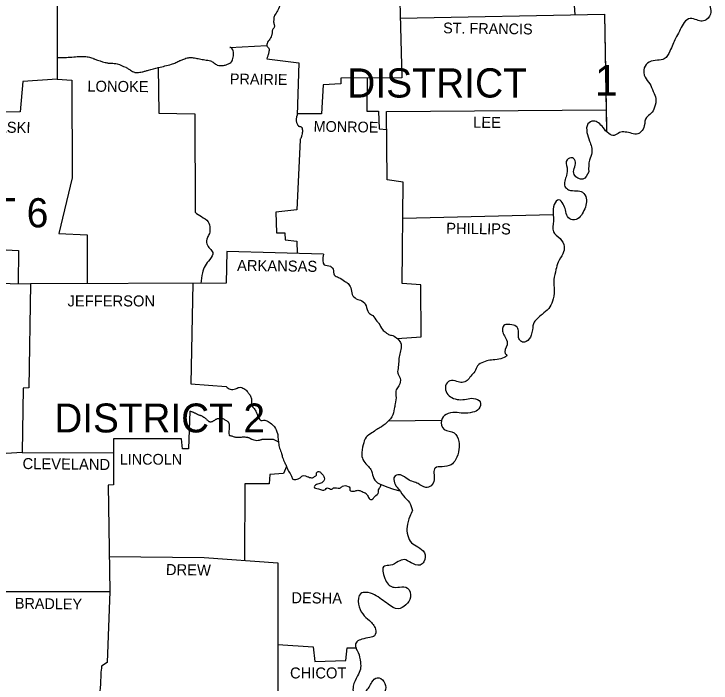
# Model space of a CAD drawing. Extents: x 6028666 to 6031787, y 5366484 to 5368484.
# Drawn here: x 6031401.8 to 6031674.1, y 5367817 to 5368078.3 of the extents above; entities that cross this region are included whole.
import ezdxf

# ---------------------------------------------------------------- set-up
doc = ezdxf.new("R2010")
doc.units = 0
doc.layers.add('2', color=7, linetype='Continuous')

msp = doc.modelspace()

# ---------------------------------------------------------------- linework, layer by layer
at = {"layer": '2'}
msp.add_line((6031548.15, 5367919.41), (6031568.9, 5367919.72), dxfattribs=at)
for points in [[(6031412.05, 5368281.89), (6031412.25, 5368257.49), (6031410.55, 5368257.39), (6031410.85, 5368232.49), (6031403.85, 5368231.49), (6031404.45, 5368224.79), (6031406.85, 5368221.69), (6031406.65, 5368213.79), (6031393.05, 5368213.29), (6031392.55, 5368201.09), (6031380.15, 5368200.69), (6031379.55, 5368185.89), (6031380.25, 5368184.69), (6031380.55, 5368161.09), (6031401.95, 5368159.69), (6031401.65, 5368107), (6031418.65, 5368106.5), (6031418.65, 5368052.9), (6031405.25, 5368051.9), (6031404.25, 5368040.1), (6031381.75, 5368040)], [(6031619.15, 5368123.08), (6031619.65, 5368084.2), (6031620.55, 5368083.6), (6031620.87, 5368078.06)], [(6031551.85, 5368108.2), (6031553.35, 5368053.4), (6031529.55, 5368053.3), (6031529.45, 5368051.1), (6031522.55, 5368050.7), (6031521.95, 5368039.3), (6031512.47, 5368039.3)], [(6031552.72, 5368076.69), (6031632.45, 5368078.3)], [(6031632.45, 5368078.3), (6031633.25, 5368034.5)], [(6031632.45, 5368078.3), (6031633.25, 5368034.5)], [(6031632.45, 5368078.3), (6031633.25, 5368034.5)], [(6031632.45, 5368078.3), (6031633.25, 5368034.5)], [(6031632.45, 5368078.3), (6031633.25, 5368034.5)], [(6031632.45, 5368078.3), (6031633.25, 5368034.5)], [(6031632.45, 5368078.3), (6031633.25, 5368034.5)], [(6031632.45, 5368078.3), (6031633.29, 5368032.49)], [(6031486.15, 5368065.3), (6031500.54, 5368065.99)], [(6031500.65, 5368060.8), (6031513.15, 5368059.2), (6031512.45, 5368038.8)], [(6031458.15, 5368057.5), (6031458.35, 5368039.6), (6031472.45, 5368039.3), (6031472.55, 5368000.9)], [(6031418.65, 5368052.9), (6031424.45, 5368052.5), (6031424.55, 5368014.3), (6031419.35, 5367992.6), (6031430.45, 5367992.1), (6031430.35, 5367972.99)], [(6031539.76, 5368053.34), (6031539.65, 5368040.4), (6031544.25, 5368040.4), (6031544.45, 5368033.5), (6031547.41, 5368033.19)], [(6031551.52, 5367951.6), (6031560.85, 5367952.2), (6031560.75, 5367972.5), (6031553.45, 5367973), (6031553.85, 5368012.7), (6031547.55, 5368013.6), (6031547.35, 5368040.3), (6031633.14, 5368040.9)], [(6031340.75, 5368027.94), (6031352.65, 5368027.2), (6031352.25, 5368014.7), (6031365.35, 5368014.2), (6031365.55, 5368003.3), (6031371.75, 5368002.8), (6031371.75, 5368000.9), (6031377.55, 5368000.5), (6031377.75, 5367993.5), (6031390.95, 5367993.5), (6031391.35, 5367986.6), (6031403.55, 5367986), (6031403.45, 5367972.98)], [(6031513.55, 5368029.2), (6031512.35, 5368001.8), (6031504.15, 5368000.9), (6031504.35, 5367992.8), (6031507.65, 5367992.9), (6031507.75, 5367990.1), (6031512.25, 5367989.6), (6031512.4, 5367984.77)], [(6031553.71, 5367998.59), (6031612.47, 5368000.05)], [(6031522.75, 5367984.5), (6031484.95, 5367985.5), (6031484.75, 5367973.2), (6031408.25, 5367972.9)], [(6031350.65, 5367959.7), (6031356.25, 5367960.5), (6031356.65, 5367963.9), (6031359.95, 5367964.5), (6031360.15, 5367966.5), (6031383.45, 5367967.2), (6031384.35, 5367973.3), (6031408.25, 5367972.9)], [(6031408.25, 5367972.9), (6031407.65, 5367932.3), (6031405.35, 5367932.2), (6031405.05, 5367907.1)], [(6031471.69, 5367973.15), (6031470.85, 5367933.9), (6031484.75, 5367932.8)], [(6031470.55, 5367923.2), (6031469.95, 5367908.5), (6031467.65, 5367908.5), (6031467.25, 5367912.4), (6031440.65, 5367912.4), (6031440.68, 5367906.9)], [(6031405.05, 5367907.1), (6031390.43, 5367906.2)], [(6031405.05, 5367907.1), (6031440.68, 5367906.9)], [(6031440.68, 5367906.9), (6031440.75, 5367894.4), (6031438.65, 5367894.3), (6031439.25, 5367852.8)], [(6031508.25, 5367901.6), (6031507.05, 5367898.9), (6031501.75, 5367898.4), (6031501.45, 5367894.8), (6031491.95, 5367894.8), (6031491.85, 5367864.9)], [(6031545.25, 5367894.5), (6031547.49, 5367893.62), (6031550.06, 5367892.73), (6031552.5, 5367892.11)], [(6031438.95, 5367866.4), (6031476.05, 5367866.1), (6031504.85, 5367863.9)], [(6031504.85, 5367863.9), (6031504.85, 5367804.1), (6031505.65, 5367746.67)], [(6031394.05, 5367852.7), (6031439.25, 5367852.8)], [(6031439.25, 5367852.8), (6031438.25, 5367825), (6031436.05, 5367823.6)], [(6031504.85, 5367832.03), (6031518.75, 5367831.2), (6031519.35, 5367825.4), (6031531.45, 5367825.8), (6031531.95, 5367830.7), (6031535.69, 5367830.7)]]:
    msp.add_lwpolyline(points, dxfattribs=at)
for points in [[(6031513.35, 5368119.8), (6031513.29, 5368118.96), (6031513.22, 5368118.14), (6031513.08, 5368117.31), (6031512.98, 5368116.9), (6031512.92, 5368116.7), (6031512.85, 5368116.5), (6031512.53, 5368116.13), (6031512.02, 5368115.95), (6031511.45, 5368115.82), (6031511.18, 5368115.73), (6031510.95, 5368115.6), (6031509.78, 5368114.56), (6031508.75, 5368113.4), (6031508.56, 5368112.92), (6031508.52, 5368112.38), (6031508.46, 5368111.85), (6031508.25, 5368111.4), (6031508.07, 5368111.24), (6031507.85, 5368111.13), (6031507.37, 5368110.99), (6031506.87, 5368110.85), (6031506.45, 5368110.6), (6031505.98, 5368110.12), (6031505.53, 5368109.62), (6031505.12, 5368109.08), (6031504.75, 5368108.5), (6031504.06, 5368107.08), (6031503.65, 5368105.6), (6031503.57, 5368104.1), (6031503.65, 5368102.6), (6031503.72, 5368101.73), (6031503.84, 5368100.88), (6031504.04, 5368100.03), (6031504.18, 5368099.61), (6031504.35, 5368099.2), (6031504.82, 5368098.79), (6031505.51, 5368098.68), (6031506.25, 5368098.6), (6031506.85, 5368098.3), (6031507.05, 5368098.07), (6031507.24, 5368097.83), (6031507.56, 5368097.34), (6031508.05, 5368096.3), (6031508.08, 5368095.78), (6031507.93, 5368095.23), (6031507.79, 5368094.69), (6031507.85, 5368094.2), (6031508.32, 5368093.76), (6031509.01, 5368093.52), (6031509.72, 5368093.27), (6031510.25, 5368092.8), (6031510.43, 5368092.5), (6031510.58, 5368092.2), (6031510.67, 5368091.9), (6031510.65, 5368091.6), (6031510.25, 5368090.3), (6031509.15, 5368086.6), (6031509.08, 5368085.98), (6031509.13, 5368085.36), (6031509.21, 5368084.73), (6031509.25, 5368084.1), (6031509.21, 5368083.54), (6031509.15, 5368083.27), (6031509.05, 5368083), (6031508.53, 5368082.62), (6031507.73, 5368082.61), (6031506.92, 5368082.62), (6031506.35, 5368082.3), (6031504.75, 5368079.6), (6031503.65, 5368077.7), (6031503.52, 5368077.39), (6031503.31, 5368076.45), (6031503.27, 5368075.82), (6031503.25, 5368075.2), (6031503.3, 5368074.75), (6031503.43, 5368074.3), (6031503.54, 5368073.85), (6031503.55, 5368073.4), (6031503.41, 5368073.03), (6031503.18, 5368072.69), (6031502.93, 5368072.35), (6031502.75, 5368072), (6031502.67, 5368071.48), (6031502.66, 5368070.93), (6031502.61, 5368070.4), (6031502.45, 5368069.9), (6031501.45, 5368068.1), (6031500.55, 5368066.4), (6031500.59, 5368065.9), (6031500.98, 5368065.41), (6031501.4, 5368064.91), (6031501.55, 5368064.4), (6031501.41, 5368063.7), (6031501.25, 5368063), (6031501.1, 5368062.44), (6031500.92, 5368061.89), (6031500.65, 5368060.8)], [(6031669.75, 5368115.8), (6031670.15, 5368112.9), (6031668.45, 5368109.8), (6031667.85, 5368106.7), (6031668.15, 5368103.6), (6031664.95, 5368101.9), (6031662.15, 5368099.9), (6031663.75, 5368097.5), (6031666.75, 5368095.3), (6031669.75, 5368093.6), (6031671.65, 5368091.9), (6031672.15, 5368087.8), (6031672.65, 5368085.2), (6031673.65, 5368081.6), (6031674.05, 5368079.1), (6031672.25, 5368076.1), (6031670.15, 5368075.5), (6031667.95, 5368076.2), (6031665.35, 5368076.4), (6031663.25, 5368074.4), (6031661.75, 5368071.6), (6031660.25, 5368068.8), (6031659.15, 5368066.4), (6031658.05, 5368063.8), (6031655.85, 5368060.8), (6031653.15, 5368060.3), (6031649.95, 5368059.5), (6031648.05, 5368057.3), (6031648.35, 5368053.6), (6031650.15, 5368051.1), (6031651.55, 5368048), (6031652.55, 5368045.3), (6031652.05, 5368041.9), (6031650.65, 5368039.4), (6031648.85, 5368037.9), (6031648.05, 5368034.7), (6031646.75, 5368032.3), (6031645.55, 5368031.5), (6031643.15, 5368031.7), (6031640.55, 5368032.2), (6031638.35, 5368032), (6031636.25, 5368030.9), (6031634.15, 5368031.6), (6031631.95, 5368034), (6031630.15, 5368035.8), (6031628.15, 5368036.5), (6031626.05, 5368035.4), (6031625.65, 5368032.1), (6031626.65, 5368028.7), (6031627.55, 5368024.1), (6031626.65, 5368021.3), (6031626.35, 5368016.7)], [(6031418.65, 5368061.29), (6031424.45, 5368061.5), (6031429.95, 5368061.7), (6031431.72, 5368061.35), (6031432.59, 5368061.01), (6031433.02, 5368060.85), (6031433.45, 5368060.7), (6031437.45, 5368059.4), (6031438.03, 5368059.26), (6031438.61, 5368059.18), (6031439.8, 5368059.1), (6031440.99, 5368059.02), (6031442.15, 5368058.8), (6031445.45, 5368057.5), (6031445.95, 5368057.25), (6031446.43, 5368056.97), (6031447.38, 5368056.34), (6031448.84, 5368055.6), (6031449.09, 5368055.54), (6031449.35, 5368055.5), (6031449.97, 5368055.47), (6031451.85, 5368055.72), (6031453.11, 5368056.06), (6031454.35, 5368056.4), (6031458.25, 5368057.4), (6031463.35, 5368058.7), (6031464.2, 5368058.98), (6031465.02, 5368059.34), (6031465.83, 5368059.74), (6031466.65, 5368060.1), (6031467.12, 5368060.29), (6031468.53, 5368060.87), (6031469.48, 5368061.16), (6031469.97, 5368061.25), (6031470.45, 5368061.3), (6031472.35, 5368061.14), (6031474.25, 5368060.8), (6031476.41, 5368060.42), (6031478.55, 5368060), (6031479.28, 5368059.7), (6031479.94, 5368059.25), (6031480.59, 5368058.76), (6031481.25, 5368058.4), (6031482.42, 5368058.16), (6031483.7, 5368058.23), (6031484.98, 5368058.56), (6031485.59, 5368058.81), (6031486.15, 5368059.1), (6031486.76, 5368059.65), (6031487.2, 5368060.47), (6031487.6, 5368062.49), (6031487.27, 5368064.37), (6031486.82, 5368065), (6031486.15, 5368065.3)], [(6031512.45, 5368038.8), (6031512.34, 5368038.55), (6031512.24, 5368038.31), (6031512.12, 5368037.8), (6031512.06, 5368037.3), (6031512.05, 5368037.05), (6031512.05, 5368036.8), (6031512.13, 5368036.26), (6031512.3, 5368035.73), (6031512.55, 5368035.21), (6031512.7, 5368034.95), (6031512.85, 5368034.7), (6031512.99, 5368034.55), (6031513.17, 5368034.46), (6031513.59, 5368034.36), (6031513.99, 5368034.26), (6031514.14, 5368034.15), (6031514.21, 5368034.08), (6031514.25, 5368034), (6031514.3, 5368033.88), (6031514.34, 5368033.75), (6031514.5, 5368033), (6031514.51, 5368032.49), (6031514.49, 5368032.24), (6031514.45, 5368032), (6031514.26, 5368030.99), (6031514.13, 5368030.49), (6031514.05, 5368030.25), (6031513.95, 5368030), (6031513.77, 5368029.59), (6031513.55, 5368029.2)], [(6031626.35, 5368016.7), (6031624.05, 5368013.8), (6031620.65, 5368015.6), (6031620.65, 5368018), (6031621.15, 5368020.5), (6031619.95, 5368022.1), (6031617.85, 5368021.4), (6031617.85, 5368018.3), (6031617.65, 5368015.3), (6031617.05, 5368011), (6031618.45, 5368009.7), (6031621.65, 5368009.3), (6031623.95, 5368008.7), (6031625.35, 5368006.4), (6031625.25, 5368003.6), (6031624.15, 5368000.9), (6031622.55, 5367998.7), (6031620.05, 5367997.9), (6031618.05, 5367999.2), (6031617.25, 5368001.8), (6031616.35, 5368004.1), (6031614.65, 5368005.8), (6031612.85, 5368003.9), (6031612.45, 5368000.4), (6031612.55, 5367997.4), (6031612.55, 5367993.3), (6031615.15, 5367990.6), (6031616.75, 5367987.5), (6031616.25, 5367984.7), (6031614.35, 5367981.4), (6031613.55, 5367978.5), (6031612.75, 5367974.6), (6031612.85, 5367970.3), (6031612.15, 5367966.1), (6031610.75, 5367963.3), (6031608.15, 5367961), (6031606.45, 5367959.5), (6031605.05, 5367958), (6031604.35, 5367955), (6031603.85, 5367952.9), (6031601.95, 5367950.4), (6031600.45, 5367950.2), (6031599.25, 5367951.2), (6031598.85, 5367952.9), (6031598.85, 5367954.6), (6031598.05, 5367956.3), (6031595.55, 5367957), (6031593.55, 5367956.9), (6031592.65, 5367955.5), (6031593.95, 5367951.6), (6031594.45, 5367949.1), (6031593.75, 5367945.7), (6031594.15, 5367945.3), (6031590.55, 5367943.4), (6031587.65, 5367943.1), (6031585.25, 5367942.4), (6031582.95, 5367940.9), (6031581.85, 5367938.7), (6031580.25, 5367936.9), (6031578.85, 5367935.2), (6031576.95, 5367934.4), (6031574.85, 5367934.8), (6031572.05, 5367935.1), (6031570.45, 5367933.1), (6031570.95, 5367930.2), (6031572.85, 5367928.5), (6031575.65, 5367927.7), (6031578.55, 5367927.9), (6031581.35, 5367928.2), (6031583.95, 5367926.8), (6031583.45, 5367924.1), (6031580.95, 5367922.8), (6031577.25, 5367922.4), (6031574.25, 5367922.7), (6031570.65, 5367921.9), (6031568.85, 5367919.6), (6031569.85, 5367916.1), (6031573.75, 5367914.7), (6031575.55, 5367911.4), (6031575.65, 5367908.3), (6031574.35, 5367904.2), (6031572.55, 5367902.3), (6031569.05, 5367901.5), (6031566.35, 5367901), (6031565.95, 5367896.4), (6031564.75, 5367894.1), (6031562.65, 5367893.4), (6031559.65, 5367894.9), (6031557.85, 5367895.6), (6031555.65, 5367896.6), (6031552.85, 5367898.3), (6031550.75, 5367898), (6031551.35, 5367893.6), (6031551.55, 5367893.4), (6031553.95, 5367890.1), (6031556.35, 5367887.5), (6031557.45, 5367884.4)], [(6031472.55, 5368000.9), (6031475.05, 5367999.2), (6031477.65, 5367997.2), (6031478.35, 5367994.5), (6031478.15, 5367992.6), (6031477.35, 5367991), (6031477.15, 5367988.5), (6031478.35, 5367986.7), (6031479.45, 5367985.2), (6031478.35, 5367982.5), (6031476.45, 5367980), (6031475.45, 5367977.2), (6031474.75, 5367973)], [(6031522.75, 5367984.5), (6031523.05, 5367980.4), (6031525.45, 5367979.8), (6031526.45, 5367978.7), (6031526.95, 5367976.4), (6031528.65, 5367975.4), (6031530.95, 5367974), (6031532.35, 5367973), (6031533.35, 5367971.4), (6031533.95, 5367968.8), (6031535.55, 5367967.1), (6031537.75, 5367966.3), (6031539.35, 5367964.4), (6031540.35, 5367961.7), (6031541.95, 5367960.5), (6031543.55, 5367958.4), (6031544.35, 5367957.5), (6031545.75, 5367955.1), (6031547.15, 5367953.9), (6031548.15, 5367953.2), (6031549.75, 5367952.7), (6031551.75, 5367951.4), (6031553.05, 5367949.4), (6031553.05, 5367947.9), (6031552.55, 5367945.6), (6031552.15, 5367943.2), (6031551.95, 5367940.5), (6031551.75, 5367938.1), (6031552.65, 5367936.1), (6031552.15, 5367933.1), (6031551.15, 5367931.5), (6031551.05, 5367929.3), (6031550.75, 5367926), (6031550.35, 5367924.1), (6031549.45, 5367921), (6031548.15, 5367919.4)], [(6031484.75, 5367932.8), (6031486.25, 5367931.8), (6031488.35, 5367931.9), (6031489.75, 5367932.5), (6031490.85, 5367932.4), (6031492.35, 5367931.5), (6031493.35, 5367930.3), (6031494.05, 5367929.4), (6031494.55, 5367928), (6031494.55, 5367926.7), (6031495.05, 5367924.9), (6031495.65, 5367924.2), (6031496.45, 5367922.9), (6031496.95, 5367921.7), (6031497.25, 5367920.9), (6031498.35, 5367919.6), (6031499.35, 5367919.7), (6031500.25, 5367919.6), (6031501.45, 5367918.9), (6031503.25, 5367917.5), (6031503.55, 5367917.1), (6031504.75, 5367914.5), (6031504.95, 5367912.9), (6031505.15, 5367910.8), (6031505.55, 5367908.8), (6031506.35, 5367906.6), (6031506.75, 5367905.1), (6031507.65, 5367903), (6031508.25, 5367901.6), (6031509.05, 5367899.8), (6031510.25, 5367897.8), (6031510.75, 5367896.6), (6031512.45, 5367896.7), (6031513.65, 5367897.2), (6031514.55, 5367898), (6031515.65, 5367897.9), (6031516.85, 5367897.5), (6031518.45, 5367897.2), (6031519.45, 5367897.8), (6031519.95, 5367898.2), (6031520.05, 5367899.1), (6031520.95, 5367899.6), (6031521.95, 5367898.9), (6031523.05, 5367897.3), (6031523.05, 5367896.3), (6031522.65, 5367895.7), (6031521.35, 5367894.9), (6031519.55, 5367894.3), (6031519.05, 5367893.6), (6031520.75, 5367892.8), (6031523.45, 5367892.6), (6031524.15, 5367893.2), (6031525.95, 5367892.7), (6031526.65, 5367893.2), (6031529.05, 5367893.1), (6031530.15, 5367893.9), (6031532.35, 5367893.8), (6031533.05, 5367893.3), (6031533.05, 5367892.4), (6031534.85, 5367892), (6031536.15, 5367892.3), (6031537.85, 5367891.8), (6031539.35, 5367891), (6031540.15, 5367889.9), (6031541.15, 5367888.7), (6031542.05, 5367889), (6031542.75, 5367889.9), (6031544.25, 5367891.5), (6031544.25, 5367892.5), (6031544.65, 5367893.2), (6031545.25, 5367894.5)], [(6031470.55, 5367923.2), (6031471.02, 5367923.1), (6031471.47, 5367922.97), (6031472.35, 5367922.6), (6031472.68, 5367922.43), (6031473.01, 5367922.25), (6031473.33, 5367922.07), (6031473.65, 5367921.9), (6031474.07, 5367921.74), (6031474.51, 5367921.62), (6031474.94, 5367921.49), (6031475.35, 5367921.3), (6031475.92, 5367920.92), (6031476.45, 5367920.5), (6031476.83, 5367920.18), (6031477.2, 5367919.84), (6031477.56, 5367919.5), (6031477.75, 5367919.34), (6031477.95, 5367919.2), (6031478.37, 5367919.06), (6031478.83, 5367919.09), (6031479.31, 5367919.22), (6031479.75, 5367919.4), (6031480.08, 5367919.59), (6031480.39, 5367919.82), (6031480.7, 5367920.04), (6031481.05, 5367920.2), (6031482.35, 5367920.4), (6031483.35, 5367920.3), (6031484.45, 5367919.7), (6031485.11, 5367919.33), (6031485.4, 5367919.11), (6031485.54, 5367918.97), (6031485.6, 5367918.89), (6031485.65, 5367918.8), (6031485.85, 5367918.16), (6031485.86, 5367917.83), (6031485.85, 5367917.5), (6031485.85, 5367916), (6031485.85, 5367913.9), (6031485.93, 5367913.76), (6031486.11, 5367913.68), (6031486.55, 5367913.6), (6031487.79, 5367913.22), (6031489.05, 5367913), (6031489.48, 5367913.01), (6031489.9, 5367913.04), (6031490.33, 5367913.08), (6031490.75, 5367913.1), (6031491.55, 5367913.12), (6031492.35, 5367913.1), (6031493.01, 5367913), (6031493.33, 5367912.91), (6031493.65, 5367912.8), (6031493.94, 5367912.66), (6031494.2, 5367912.49), (6031494.47, 5367912.33), (6031494.75, 5367912.2), (6031495.55, 5367912), (6031496.75, 5367911.8), (6031497.75, 5367911.9), (6031498.18, 5367912.01), (6031498.6, 5367912.14), (6031499.02, 5367912.25), (6031499.45, 5367912.3), (6031500.45, 5367912.3), (6031502.05, 5367912.3), (6031502.55, 5367912.27), (6031502.8, 5367912.24), (6031503.05, 5367912.2), (6031504.12, 5367911.8), (6031504.63, 5367911.49), (6031505.11, 5367911.16)], [(6031548.15, 5367919.4), (6031545.35, 5367917.1), (6031543.55, 5367916.1), (6031541.65, 5367914.7), (6031539.35, 5367913), (6031538.25, 5367910.1), (6031537.65, 5367906.1), (6031538.45, 5367903.7), (6031540.25, 5367901.6), (6031541.45, 5367899.9), (6031542.35, 5367896.9), (6031544.55, 5367894.8), (6031545.25, 5367894.5)], [(6031557.45, 5367884.4), (6031556.45, 5367882.1), (6031555.35, 5367878.1), (6031555.65, 5367874.7), (6031557.15, 5367871.8), (6031559.55, 5367870.2), (6031562.15, 5367867.9), (6031561.95, 5367864.4), (6031560.45, 5367863.1), (6031556.95, 5367864), (6031554.25, 5367865.2), (6031551.95, 5367864.5), (6031548.85, 5367863), (6031546.55, 5367862.7), (6031546.65, 5367857.9), (6031549.75, 5367854.5), (6031552.45, 5367854.5), (6031555.55, 5367854.1), (6031556.65, 5367850.5), (6031554.85, 5367847.5), (6031551.85, 5367846), (6031548.05, 5367847.8), (6031545.35, 5367849.7), (6031542.65, 5367851.5), (6031539.25, 5367852.4), (6031537.35, 5367852), (6031536.45, 5367847.8), (6031538.05, 5367844), (6031540.65, 5367841.4), (6031543.05, 5367838), (6031542.65, 5367835.5), (6031540.85, 5367834.8), (6031537.65, 5367834.1), (6031535.75, 5367833.1), (6031535.25, 5367832.3), (6031536.25, 5367828.9), (6031537.15, 5367825.2), (6031537.15, 5367822.4), (6031536.05, 5367819.8), (6031534.35, 5367815.8), (6031534.55, 5367813.2), (6031535.75, 5367812), (6031537.25, 5367812.4), (6031539.25, 5367813.8), (6031540.55, 5367815.4), (6031541.65, 5367817.4), (6031543.75, 5367819.1), (6031546.35, 5367817.6), (6031546.95, 5367814.5), (6031545.45, 5367811.8), (6031543.35, 5367810.6), (6031540.75, 5367809.6), (6031538.85, 5367807.4), (6031539.35, 5367804.8), (6031540.85, 5367803.4), (6031544.55, 5367804.1), (6031547.05, 5367805.2), (6031548.45, 5367806.6), (6031550.15, 5367808.3), (6031551.05, 5367810), (6031552.35, 5367811.8), (6031554.65, 5367812.3), (6031555.75, 5367810.8), (6031555.35, 5367807.4), (6031553.95, 5367804.2), (6031552.05, 5367801.5), (6031549.95, 5367799.6), (6031547.35, 5367795.5), (6031547.85, 5367791.7), (6031548.85, 5367788.6), (6031550.25, 5367786.2), (6031552.65, 5367786.7), (6031555.35, 5367787), (6031556.95, 5367785.7), (6031556.75, 5367782.9), (6031554.75, 5367780.2), (6031552.85, 5367777.61), (6031551.85, 5367774.01), (6031552.25, 5367771.51), (6031552.25, 5367769.21), (6031551.45, 5367766.71), (6031550.05, 5367765.31), (6031546.35, 5367765.41), (6031542.45, 5367765.81), (6031540.35, 5367764.61), (6031540.75, 5367761.21), (6031543.05, 5367758.71), (6031544.65, 5367757.41), (6031546.95, 5367754.61), (6031547.95, 5367752.31), (6031547.65, 5367750.31), (6031546.25, 5367748.61), (6031542.15, 5367746.61)], [(6031436.05, 5367823.6), (6031435.75, 5367820.5), (6031435.65, 5367817.6), (6031435.45, 5367814.8), (6031435.4, 5367813.75), (6031435.4, 5367813.23), (6031435.45, 5367812.7), (6031435.65, 5367812.1), (6031436, 5367811.54), (6031436.37, 5367810.99), (6031436.65, 5367810.4), (6031437.35, 5367808.2), (6031438.05, 5367806.3), (6031439.45, 5367803.8), (6031439.76, 5367803.32), (6031440.1, 5367802.86), (6031440.44, 5367802.39), (6031440.75, 5367801.9), (6031441.26, 5367800.56), (6031441.31, 5367799.86), (6031441.15, 5367799.2), (6031440.35, 5367797.8), (6031439.99, 5367797.27), (6031439.6, 5367796.75), (6031439.21, 5367796.23), (6031438.85, 5367795.7), (6031438.69, 5367794.79), (6031438.9, 5367793.75), (6031439.07, 5367792.73), (6031438.75, 5367791.9), (6031438.55, 5367791.72), (6031438.33, 5367791.57), (6031437.86, 5367791.29), (6031437.39, 5367791.01), (6031436.95, 5367790.7), (6031435.82, 5367789.69), (6031435.25, 5367789.18), (6031434.65, 5367788.7), (6031433.35, 5367787.8), (6031431.95, 5367786.9), (6031431.54, 5367786.55), (6031431.18, 5367786.13), (6031430.83, 5367785.7), (6031430.45, 5367785.3), (6031429.92, 5367784.91), (6031429.34, 5367784.58), (6031428.76, 5367784.23), (6031428.25, 5367783.8), (6031427.81, 5367783.22), (6031427.44, 5367782.57), (6031427.07, 5367781.92), (6031426.65, 5367781.3), (6031426.24, 5367780.8), (6031425.81, 5367780.3), (6031424.85, 5367779.41), (6031423.35, 5367778.41), (6031422.83, 5367778.09), (6031422.3, 5367777.78), (6031421.51, 5367777.29), (6031421.25, 5367777.11), (6031420.89, 5367776.7), (6031420.65, 5367776.2), (6031420.35, 5367775.11), (6031420.09, 5367774.18), (6031419.85, 5367773.26), (6031419.69, 5367772.34), (6031419.65, 5367771.41), (6031419.77, 5367770.05), (6031419.95, 5367768.71), (6031420.35, 5367766.31), (6031420.31, 5367765.56), (6031420.1, 5367764.81), (6031419.9, 5367764.06), (6031419.85, 5367763.31), (6031420.35, 5367760.01), (6031420.85, 5367757.41), (6031421.65, 5367755.11), (6031422.75, 5367752.51), (6031423.41, 5367751.28), (6031424.15, 5367750.11), (6031425.41, 5367748.4), (6031426.79, 5367746.79)]]:
    msp.add_spline(points, degree=3, dxfattribs=at)

# ---------------------------------------------------------------- texts
for s, height, rotation, p in [('ST. FRANCIS', 4.1992, 359.2216, (6031569.45, 5368070.8)), ('PRAIRIE', 4.2, 359.2116, (6031486.15, 5368050.9)), ('LONOKE', 4.301, 359.4974, (6031430.45, 5368048)), ('LEE', 4.301, 359.4327, (6031581.15, 5368033.9)), ('PULASKI', 4.301, 359.0531, (6031383.95, 5368032.2)), ('MONROE', 4.199, 359.0331, (6031518.85, 5368032.4)), ('PHILLIPS', 4.299, 359.318, (6031570.65, 5367992.5)), ('ARKANSAS', 4.299, 359.2678, (6031488.95, 5367978)), ('CLEVELAND', 4.301, 359.3377, (6031405.15, 5367900.6)), ('DREW', 4.299, 359.2258, (6031461.15, 5367859.2)), ('BRADLEY', 4.199, 359.1449, (6031402.15, 5367846.1)), ('DESHA', 4.299, 359.3704, (6031510.15, 5367848.2))]:
    msp.add_text(s, height=height, rotation=rotation, dxfattribs=at).set_placement(p)
for s, height, p in [('DISTRICT', 11.4, (6031531.95, 5368045.7)), ('1', 12, (6031628.75, 5368046.4)), ('DISTRICT 6', 11.4, (6031332.25, 5367995)), ('JEFFERSON', 4.3, (6031422.75, 5367964.1)), ('DISTRICT 2', 11.299, (6031417.6, 5367914.89)), ('LINCOLN', 4.2, (6031443.15, 5367902.3)), ('CHICOT', 4.3, (6031509.65, 5367818.8))]:
    msp.add_text(s, height=height, dxfattribs=at).set_placement(p)

doc.saveas('drawing.dxf')
